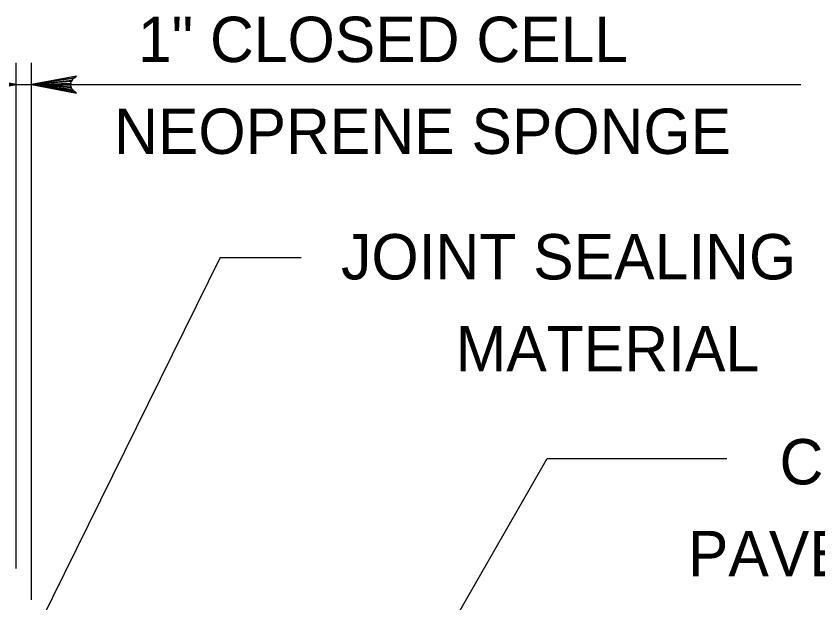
# Model space of a CAD drawing. Extents: x 2084213 to 2099800, y 976677 to 981262.
# Drawn here: x 2094550.7 to 2094724.7, y 977118.3 to 977245.6 of the extents above; entities that cross this region are included whole.
import ezdxf

# ---------------------------------------------------------------- set-up
doc = ezdxf.new("R2010")
doc.units = 0
doc.layers.add('1', color=7, linetype='Continuous')

msp = doc.modelspace()

# ---------------------------------------------------------------- linework, layer by layer
at = {"layer": '1'}
for p, q in [((2094550.71, 977125.76), (2094550.71, 977235.47)), ((2094554.05, 977118.97), (2094554.05, 977235.47)), ((2094534.84, 977230.73), (2094720.95, 977230.73)), ((2094594.99, 977193.27), (2094552.07, 977106.28)), ((2094594.99, 977193.27), (2094612.58, 977193.27)), ((2094631.96, 977090.51), (2094665.97, 977149.63)), ((2094665.97, 977149.63), (2094704.94, 977149.63))]:
    msp.add_line(p, q, dxfattribs=at)
for points in [[(2094550.71, 977230.73), (2094540.93, 977232.56)], [(2094541.68, 977232.04), (2094550.71, 977230.73), (2094541.31, 977232.3)], [(2094542.07, 977231.39), (2094550.71, 977230.73), (2094541.88, 977231.71)], [(2094542.18, 977230.73), (2094550.71, 977230.73), (2094542.13, 977231.06)], [(2094554.05, 977230.73), (2094563.83, 977228.9), (2094563.46, 977229.16), (2094563.08, 977229.42), (2094562.88, 977229.75), (2094562.69, 977230.07), (2094562.63, 977230.4), (2094562.58, 977230.73), (2094562.63, 977231.06), (2094562.69, 977231.39), (2094562.88, 977231.71), (2094563.08, 977232.04), (2094563.46, 977232.3), (2094563.83, 977232.56), (2094554.05, 977230.73), (2094563.46, 977232.3), (2094563.08, 977232.04), (2094554.05, 977230.73), (2094562.88, 977231.71), (2094562.69, 977231.39), (2094554.05, 977230.73), (2094562.63, 977231.06), (2094562.58, 977230.73), (2094554.05, 977230.73), (2094562.63, 977230.4), (2094562.69, 977230.07), (2094554.05, 977230.73), (2094562.88, 977229.75), (2094563.08, 977229.42), (2094554.05, 977230.73), (2094563.46, 977229.16)], [(2094540.93, 977228.9), (2094550.71, 977230.73), (2094541.31, 977229.16)], [(2094541.68, 977229.42), (2094550.71, 977230.73), (2094541.88, 977229.75)], [(2094542.07, 977230.07), (2094550.71, 977230.73), (2094542.13, 977230.4)]]:
    msp.add_lwpolyline(points, dxfattribs=at)

# ---------------------------------------------------------------- texts
for s, height, p in [('1" CLOSED CELL', 9.8425, (2094577.15, 977235.63)), ('NEOPRENE SPONGE', 9.8425, (2094571.99, 977215.7)), ('JOINT SEALING', 9.8425, (2094621.23, 977188.48)), ('MATERIAL', 9.843, (2094646.11, 977168.56)), ('CONCRETE SLAB FOR', 9.8425, (2094716.35, 977144.01)), ('PAVEMENT RELIEF JOINT', 9.8425, (2094696.47, 977124.09))]:
    msp.add_text(s, height=height, dxfattribs=at).set_placement(p)

doc.saveas('drawing.dxf')
